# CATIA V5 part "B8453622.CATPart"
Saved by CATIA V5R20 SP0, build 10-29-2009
Part number: B8453622
Revision: 2
Definition: design
Nomenclature: B8453622
Source: made
Description: NOT SPECIFIED
Bounding box of the stored display mesh (mm): x -29 to 29, y -29 to 29, z -17 to 22
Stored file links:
  C:\Users\Utente\Desktop\3D files B845\B8453622.CATPart
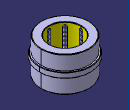
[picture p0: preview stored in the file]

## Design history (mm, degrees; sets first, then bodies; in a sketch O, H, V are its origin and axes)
Body1 "MANIFOLD_SOLID_BREP #38" (main body)
  Solid1: solid without history
Body2 "MANIFOLD_SOLID_BREP #76"
  Solid2: solid without history
Body3 "MANIFOLD_SOLID_BREP #114"
  Solid3: solid without history
Body4 "MANIFOLD_SOLID_BREP #152"
  Solid4: solid without history
Body5 "MANIFOLD_SOLID_BREP #190"
  Solid5: solid without history
Body6 "MANIFOLD_SOLID_BREP #2288"
  Solid6: solid without history
Body7 "MANIFOLD_SOLID_BREP #2326"
  Solid7: solid without history
Body8 "MANIFOLD_SOLID_BREP #2364"
  Solid8: solid without history
Body9 "MANIFOLD_SOLID_BREP #2402"
  Solid9: solid without history
Body10 "MANIFOLD_SOLID_BREP #2440"
  Solid10: solid without history
Body11 "MANIFOLD_SOLID_BREP #2478"
  Solid11: solid without history
Body12 "MANIFOLD_SOLID_BREP #2516"
  Solid12: solid without history
Body13 "MANIFOLD_SOLID_BREP #2554"
  Solid13: solid without history
Body14 "MANIFOLD_SOLID_BREP #2592"
  Solid14: solid without history
Body15 "MANIFOLD_SOLID_BREP #2630"
  Solid15: solid without history
Body16 "MANIFOLD_SOLID_BREP #2668"
  Solid16: solid without history
Body17 "MANIFOLD_SOLID_BREP #2706"
  Solid17: solid without history
Body18 "MANIFOLD_SOLID_BREP #2744"
  Solid18: solid without history
Body19 "MANIFOLD_SOLID_BREP #2782"
  Solid19: solid without history
Body20 "MANIFOLD_SOLID_BREP #2820"
  Solid20: solid without history
Body21 "MANIFOLD_SOLID_BREP #2858"
  Solid21: solid without history
Body22 "MANIFOLD_SOLID_BREP #2896"
  Solid22: solid without history
Body23 "MANIFOLD_SOLID_BREP #2934"
  Solid23: solid without history
Body24 "MANIFOLD_SOLID_BREP #2972"
  Solid24: solid without history
Body25 "MANIFOLD_SOLID_BREP #3010"
  Solid25: solid without history
Body26 "MANIFOLD_SOLID_BREP #3048"
  Solid26: solid without history
Body27 "MANIFOLD_SOLID_BREP #3086"
  Solid27: solid without history
Body28 "MANIFOLD_SOLID_BREP #3124"
  Solid28: solid without history
Body29 "MANIFOLD_SOLID_BREP #3162"
  Solid29: solid without history
Body30 "MANIFOLD_SOLID_BREP #3200"
  Solid30: solid without history
Body31 "MANIFOLD_SOLID_BREP #3238"
  Solid31: solid without history
Body32 "MANIFOLD_SOLID_BREP #3276"
  Solid32: solid without history
Body33 "MANIFOLD_SOLID_BREP #3314"
  Solid33: solid without history
Body34 "MANIFOLD_SOLID_BREP #3352"
  Solid34: solid without history
Body35 "MANIFOLD_SOLID_BREP #3390"
  Solid35: solid without history
Body36 "MANIFOLD_SOLID_BREP #3428"
  Solid36: solid without history
Body37 "MANIFOLD_SOLID_BREP #3466"
  Solid37: solid without history
Body38 "MANIFOLD_SOLID_BREP #3504"
  Solid38: solid without history
Body39 "MANIFOLD_SOLID_BREP #3542"
  Solid39: solid without history
Body40 "MANIFOLD_SOLID_BREP #3580"
  Solid40: solid without history
Body41 "MANIFOLD_SOLID_BREP #3618"
  Solid41: solid without history
Body42 "MANIFOLD_SOLID_BREP #3656"
  Solid42: solid without history
Body43 "MANIFOLD_SOLID_BREP #3694"
  Solid43: solid without history
Body44 "MANIFOLD_SOLID_BREP #3732"
  Solid44: solid without history
Body45 "MANIFOLD_SOLID_BREP #3770"
  Solid45: solid without history
Body46 "MANIFOLD_SOLID_BREP #3808"
  Solid46: solid without history
Body47 "MANIFOLD_SOLID_BREP #3846"
  Solid47: solid without history
Body48 "MANIFOLD_SOLID_BREP #3884"
  Solid48: solid without history
Body49 "MANIFOLD_SOLID_BREP #3922"
  Solid49: solid without history
Body50 "MANIFOLD_SOLID_BREP #3960"
  Solid50: solid without history
Body51 "MANIFOLD_SOLID_BREP #3998"
  Solid51: solid without history
Body52 "MANIFOLD_SOLID_BREP #4036"
  Solid52: solid without history
Body53 "MANIFOLD_SOLID_BREP #4074"
  Solid53: solid without history
Body54 "MANIFOLD_SOLID_BREP #4112"
  Solid54: solid without history
Body55 "MANIFOLD_SOLID_BREP #4150"
  Solid55: solid without history
Body56 "MANIFOLD_SOLID_BREP #4188"
  Solid56: solid without history
Body57 "MANIFOLD_SOLID_BREP #4226"
  Solid57: solid without history
Body58 "MANIFOLD_SOLID_BREP #4264"
  Solid58: solid without history
Body59 "MANIFOLD_SOLID_BREP #4302"
  Solid59: solid without history
Body60 "MANIFOLD_SOLID_BREP #4340"
  Solid60: solid without history
Body61 "MANIFOLD_SOLID_BREP #4378"
  Solid61: solid without history
Body62 "MANIFOLD_SOLID_BREP #4416"
  Solid62: solid without history
Body63 "MANIFOLD_SOLID_BREP #4454"
  Solid63: solid without history
Body64 "MANIFOLD_SOLID_BREP #4492"
  Solid64: solid without history
Body65 "MANIFOLD_SOLID_BREP #4530"
  Solid65: solid without history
